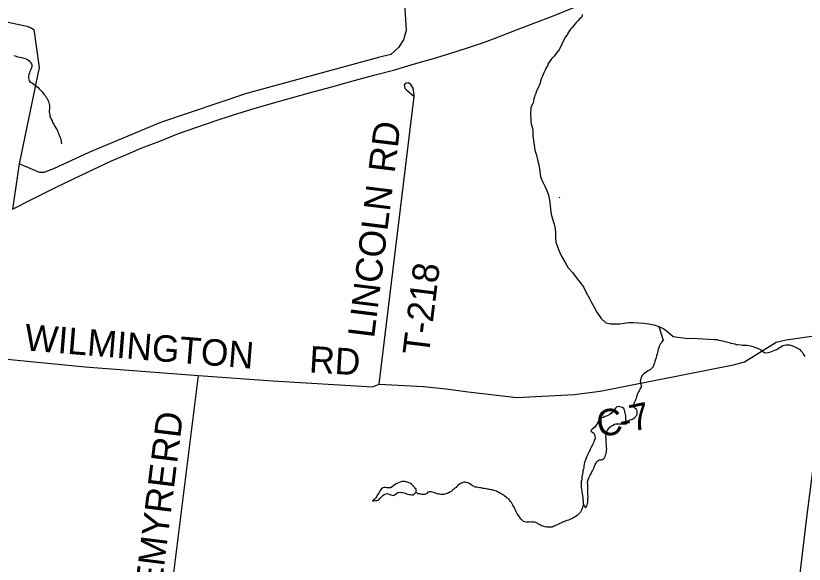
# Model space of a CAD drawing. Extents: x 0.4 to 34.4, y -2.1 to 19.9.
# Drawn here: x 5.402 to 7.097, y 14.193 to 15.372 of the extents above; entities that cross this region are included whole.
import ezdxf

# ---------------------------------------------------------------- set-up
doc = ezdxf.new("R2010")
doc.units = 0
for name, color, linetype in [('GM_X_County_Road', 7, 'Continuous'), ('GM_X_County_Road_Text', 7, 'Continuous'), ('GM_X_Interstate_Route', 7, 'Continuous'), ('GM_X_Minor_Lake', 7, 'Continuous'), ('GM_X_Minor_River', 7, 'Continuous'), ('GM_X_Township_Road', 7, 'Continuous'), ('GM_X_Township_Road_Text', 7, 'Continuous')]:
    doc.layers.add(name, color=color, linetype=linetype)

msp = doc.modelspace()

# ---------------------------------------------------------------- linework, layer by layer
at = {"layer": 'GM_X_County_Road'}
for points in [[(6.4553, 16.1829), (6.4553, 16.1828), (6.4575, 16.1516), (6.4573, 16.1428), (6.5066, 15.488), (6.5033, 15.474), (6.4918, 15.4678), (6.2441, 15.51), (6.2361, 15.5067), (6.232, 15.492), (6.2416, 15.34), (6.2359, 15.3204), (6.2246, 15.3035), (6.208, 15.2886), (6.1821, 15.2819), (5.8983, 15.2045), (5.7135, 15.1423), (5.5589, 15.0776), (5.4835, 15.0426), (5.4621, 15.035), (5.453, 15.0352), (5.438, 15.0411), (5.4094, 15.0538)], [(5.1472, 16.0652), (5.1472, 16.0652), (5.1927, 15.4283), (5.1962, 15.413), (5.2017, 15.4034), (5.2182, 15.394), (5.4257, 15.3499), (5.4355, 15.3459), (5.4407, 15.3424), (5.4524, 15.2606), (5.4094, 15.0538), (5.3948, 14.9559)], [(5.3532, 14.6364), (5.551, 14.6173), (5.7946, 14.5981), (5.9549, 14.5868), (6.1689, 14.5743), (6.183, 14.58), (6.2787, 14.5749), (6.327, 14.5697), (6.3748, 14.5632), (6.4792, 14.5513), (6.6022, 14.5578), (6.6586, 14.5646), (6.9447, 14.6216), (6.9686, 14.6277), (7.0369, 14.6701), (7.058, 14.675), (7.1535, 14.6887)]]:
    msp.add_lwpolyline(points, dxfattribs=at)
at = {"layer": 'GM_X_Interstate_Route'}
msp.add_lwpolyline([(5.3948, 14.9559), (5.4385, 14.9781), (5.4875, 15.0026), (5.5279, 15.0219), (5.5682, 15.0412), (5.6082, 15.0597), (5.642, 15.0742), (5.6732, 15.0879), (5.7116, 15.1026), (5.7519, 15.1185), (5.791, 15.1325), (5.8309, 15.1458), (5.8678, 15.1579), (5.9092, 15.1711), (5.9536, 15.184), (5.995, 15.1957), (6.0356, 15.207), (6.0812, 15.2194), (6.1245, 15.2311), (6.172, 15.2439), (6.2137, 15.2549), (6.2593, 15.2684), (6.3003, 15.2801), (6.3353, 15.2908), (6.3729, 15.3029), (6.4116, 15.3162), (6.4455, 15.3287), (6.4785, 15.342), (6.5181, 15.3564), (6.5561, 15.3712), (6.6089, 15.3922)], dxfattribs=at)
at = {"layer": 'GM_X_Minor_Lake'}
for points in [[(6.7148, 14.497), (6.7138, 14.5046), (6.7135, 14.5077), (6.7132, 14.5115), (6.7128, 14.5145), (6.7122, 14.5176), (6.7115, 14.521), (6.7104, 14.5237), (6.7089, 14.5272), (6.7063, 14.5299), (6.7029, 14.5307), (6.6999, 14.5311), (6.6972, 14.5316), (6.6941, 14.5308), (6.6914, 14.5282), (6.6894, 14.5252), (6.6871, 14.5222), (6.6832, 14.5181), (6.6789, 14.5148), (6.6762, 14.5133), (6.672, 14.5107), (6.6685, 14.51), (6.6654, 14.5085), (6.6627, 14.5074), (6.66, 14.5064), (6.6562, 14.5034), (6.6538, 14.4992), (6.6526, 14.4962), (6.651, 14.4936), (6.6486, 14.4898), (6.6467, 14.4872), (6.6428, 14.4838), (6.6389, 14.4809), (6.6381, 14.4782), (6.6415, 14.4763), (6.6448, 14.4743), (6.6463, 14.4716), (6.647, 14.4682), (6.6473, 14.4655), (6.6468, 14.4617), (6.6456, 14.4591), (6.6448, 14.4564), (6.644, 14.4538), (6.6428, 14.4511), (6.6408, 14.4481), (6.6396, 14.4455), (6.6376, 14.4417), (6.636, 14.4375), (6.6348, 14.4349), (6.632, 14.4296)], [(6.6223, 14.3215), (6.626, 14.3148), (6.6287, 14.3167), (6.6307, 14.3204), (6.6312, 14.3235), (6.6316, 14.3269), (6.6317, 14.3296), (6.6321, 14.3334), (6.6322, 14.3368), (6.6323, 14.3398), (6.632, 14.3429), (6.632, 14.3459), (6.6321, 14.3486), (6.6318, 14.352), (6.6319, 14.3547), (6.6319, 14.3585), (6.632, 14.3619), (6.6317, 14.3646), (6.6314, 14.3684), (6.6319, 14.3718), (6.6327, 14.3744), (6.6339, 14.3782), (6.6351, 14.3816), (6.6367, 14.3843), (6.6387, 14.3876), (6.6403, 14.391), (6.6419, 14.3937), (6.6431, 14.3963), (6.6451, 14.4008), (6.6463, 14.4035), (6.6475, 14.4069), (6.6491, 14.4095), (6.6507, 14.4129), (6.6542, 14.4159), (6.6569, 14.417), (6.6603, 14.4173), (6.663, 14.4176), (6.6661, 14.4199), (6.6681, 14.4225), (6.6693, 14.4251), (6.6701, 14.4278), (6.6713, 14.4308), (6.6718, 14.4342), (6.6722, 14.438), (6.6723, 14.4418), (6.672, 14.4445), (6.6721, 14.4479), (6.6718, 14.4506), (6.6715, 14.454), (6.6711, 14.4567), (6.6712, 14.4593), (6.6709, 14.4628), (6.6706, 14.4654), (6.6706, 14.4681), (6.6715, 14.4708), (6.6719, 14.4742), (6.6727, 14.4772), (6.6743, 14.4806), (6.6767, 14.4844), (6.6791, 14.4874), (6.6829, 14.49), (6.6864, 14.4918), (6.6891, 14.4936), (6.6922, 14.4947), (6.696, 14.4947), (6.7002, 14.4946), (6.7029, 14.4945), (6.7059, 14.4945), (6.7086, 14.4944), (6.7113, 14.4944), (6.7151, 14.4943)], [(6.7151, 14.4943), (6.7148, 14.497)], [(6.632, 14.4296), (6.6304, 14.4258), (6.6292, 14.4232), (6.6272, 14.4187), (6.626, 14.4153), (6.6248, 14.4119), (6.6239, 14.4081), (6.6234, 14.4039), (6.623, 14.4005), (6.6222, 14.3978), (6.6209, 14.3925), (6.62, 14.3865), (6.6199, 14.3838), (6.6191, 14.3812), (6.6186, 14.3743), (6.6177, 14.3709), (6.6173, 14.3663), (6.6175, 14.3618), (6.6174, 14.3576), (6.6181, 14.3542), (6.6188, 14.35), (6.6191, 14.3473), (6.6198, 14.3446), (6.6205, 14.34), (6.6208, 14.3362), (6.6214, 14.332), (6.6218, 14.3294), (6.6217, 14.3267), (6.622, 14.3236), (6.6223, 14.3215)], [(6.263, 14.3477), (6.2631, 14.3504), (6.2628, 14.3538), (6.2602, 14.3565), (6.2587, 14.3592), (6.2557, 14.3619), (6.2531, 14.365), (6.2493, 14.367), (6.2459, 14.3682), (6.2414, 14.3698), (6.2387, 14.3703), (6.2349, 14.3703), (6.2322, 14.3704), (6.2284, 14.3693), (6.2249, 14.3678), (6.2215, 14.366), (6.2176, 14.3638), (6.2149, 14.3619), (6.211, 14.359), (6.2075, 14.3571), (6.2037, 14.3568), (6.1999, 14.3569), (6.1969, 14.3573), (6.1942, 14.3577), (6.1908, 14.3571), (6.1877, 14.3541), (6.1857, 14.3511), (6.1841, 14.3484), (6.1825, 14.3458), (6.1793, 14.3409), (6.1774, 14.3379), (6.1754, 14.3349), (6.1723, 14.3315), (6.1692, 14.3289), (6.1726, 14.3288), (6.1757, 14.3296), (6.1791, 14.3299), (6.1822, 14.3313), (6.1849, 14.3343), (6.188, 14.3377), (6.1912, 14.3407), (6.1943, 14.3425), (6.1977, 14.344), (6.2004, 14.3447), (6.2042, 14.3435), (6.2083, 14.3419), (6.2114, 14.3411), (6.2148, 14.3406), (6.2162, 14.3418)], [(6.2162, 14.3418), (6.2202, 14.3447), (6.2237, 14.3469), (6.2279, 14.3476), (6.2313, 14.3472), (6.234, 14.3467), (6.2367, 14.3463), (6.2408, 14.3447), (6.2442, 14.3435), (6.2476, 14.3423), (6.2503, 14.3423), (6.2537, 14.3422), (6.2572, 14.3418), (6.263, 14.3477)]]:
    msp.add_lwpolyline(points, dxfattribs=at)
at = {"layer": 'GM_X_Minor_River'}
for points in [[(6.62, 15.3744), (6.6192, 15.3717), (6.6187, 15.369), (6.6148, 15.3657), (6.6113, 15.362), (6.6066, 15.3571), (6.6043, 15.3545), (6.6008, 15.35), (6.5976, 15.3462), (6.5945, 15.3429), (6.5914, 15.3387), (6.5886, 15.3346), (6.5878, 15.3316), (6.5831, 15.3259), (6.5807, 15.321), (6.5779, 15.3158), (6.5751, 15.3097), (6.5727, 15.3044), (6.5703, 15.2995), (6.5687, 15.2969), (6.5655, 15.2928), (6.5624, 15.2883), (6.5593, 15.2849), (6.5546, 15.2797), (6.5522, 15.277), (6.5487, 15.2721), (6.5459, 15.2676), (6.5455, 15.265), (6.5415, 15.259), (6.5403, 15.2552), (6.5371, 15.2491), (6.5359, 15.2457), (6.5343, 15.2423), (6.5327, 15.239), (6.5315, 15.2356), (6.5302, 15.2318), (6.529, 15.2272), (6.527, 15.2219), (6.5258, 15.2193), (6.5234, 15.2144), (6.5222, 15.2117), (6.521, 15.2083), (6.5197, 15.2049), (6.5181, 15.2004), (6.5173, 15.1974), (6.516, 15.1932), (6.5143, 15.1849), (6.5127, 15.1815), (6.5103, 15.1766), (6.5091, 15.1736), (6.509, 15.1694), (6.5085, 15.1637), (6.5088, 15.1572), (6.509, 15.1515), (6.5093, 15.1473), (6.5096, 15.1446), (6.5103, 15.1397), (6.5117, 15.1343), (6.5127, 15.1305), (6.5134, 15.1259), (6.5137, 15.1243)], [(5.3979, 15.2864), (5.4029, 15.2851), (5.4055, 15.2839), (5.4112, 15.2827), (5.4142, 15.2819), (5.4195, 15.2806), (5.4226, 15.2802), (5.426, 15.2786), (5.4294, 15.2767), (5.4324, 15.2743), (5.4338, 15.2716), (5.4361, 15.2689), (5.4368, 15.2662), (5.4367, 15.2632), (5.4362, 15.2602), (5.4354, 15.2575), (5.4326, 15.2522), (5.4314, 15.2492), (5.4298, 15.2454), (5.4294, 15.2416), (5.4293, 15.2382), (5.43, 15.2355), (5.4307, 15.2329)], [(5.4307, 15.2329), (5.4329, 15.2294), (5.4355, 15.2282), (5.4382, 15.227), (5.4412, 15.2247), (5.4445, 15.222), (5.4472, 15.2196), (5.4502, 15.2177), (5.4524, 15.2146), (5.4557, 15.2115), (5.458, 15.2088), (5.4602, 15.2061), (5.4624, 15.203), (5.465, 15.2003), (5.4676, 15.1964), (5.4695, 15.1937), (5.4713, 15.1906), (5.4724, 15.1876), (5.4734, 15.1845), (5.4741, 15.1818), (5.4745, 15.1792), (5.4744, 15.1754), (5.4743, 15.1716), (5.4742, 15.1678), (5.4741, 15.1647), (5.4745, 15.1617), (5.4752, 15.1586), (5.4755, 15.1556), (5.4769, 15.1529), (5.4784, 15.1494), (5.4802, 15.146), (5.4813, 15.1425), (5.4839, 15.139), (5.4853, 15.1356), (5.4868, 15.1329), (5.4886, 15.1294), (5.4908, 15.1264), (5.4927, 15.1229), (5.4934, 15.1202), (5.4948, 15.1172), (5.4966, 15.1114), (5.4981, 15.1087), (5.4987, 15.1053), (5.4994, 15.1026), (5.4998, 15.0999), (5.5001, 15.0969)], [(6.5137, 15.1243), (6.5137, 15.1136), (6.5151, 15.1037), (6.5164, 15.0934), (6.5182, 15.0828), (6.5211, 15.0721), (6.5239, 15.0618), (6.5268, 15.0515), (6.5285, 15.0379), (6.5302, 15.0257), (6.5342, 15.0154), (6.5394, 15.0054), (6.5438, 14.9959), (6.5474, 14.986), (6.5492, 14.9757), (6.5509, 14.9647), (6.5519, 14.9552), (6.5533, 14.9453), (6.5561, 14.935), (6.5594, 14.9236), (6.5619, 14.9137), (6.5621, 14.9042), (6.562, 14.8947), (6.563, 14.8852), (6.5666, 14.8753), (6.571, 14.8642), (6.5762, 14.8539), (6.5824, 14.8428), (6.5898, 14.8302), (6.5988, 14.8198), (6.6066, 14.8094), (6.6144, 14.7991), (6.6222, 14.7891), (6.6285, 14.7772), (6.6348, 14.7657), (6.6399, 14.7554), (6.6462, 14.7443), (6.6514, 14.7344), (6.6607, 14.7213), (6.6704, 14.7117), (6.6802, 14.7096), (6.6901, 14.7095), (6.7003, 14.7097), (6.7102, 14.7107), (6.7197, 14.7121), (6.7292, 14.7127), (6.741, 14.7117), (6.7512, 14.7112), (6.7626, 14.7099), (6.7739, 14.7074), (6.7841, 14.7038), (6.7951, 14.6991), (6.8048, 14.6914), (6.8153, 14.6821), (6.8255, 14.6808), (6.8369, 14.6791), (6.8471, 14.6778), (6.8555, 14.6784)], [(6.57, 14.9807), (6.5717, 14.9818)], [(6.7841, 14.7038), (6.7934, 14.6744), (6.7911, 14.671), (6.7891, 14.668), (6.7872, 14.6658), (6.7855, 14.6616), (6.7843, 14.6586), (6.7835, 14.6563), (6.7831, 14.654), (6.7823, 14.6518), (6.7814, 14.648), (6.7806, 14.6449), (6.7797, 14.6408), (6.7785, 14.6381), (6.7777, 14.634), (6.7768, 14.6313), (6.776, 14.629), (6.7752, 14.6249), (6.774, 14.6219), (6.7728, 14.6196), (6.772, 14.6173), (6.77, 14.6151), (6.7677, 14.6128), (6.7657, 14.6106), (6.763, 14.6091), (6.7603, 14.608), (6.7572, 14.6054), (6.7545, 14.6036), (6.7518, 14.6013), (6.7494, 14.5991), (6.7475, 14.5965), (6.7463, 14.5938), (6.7455, 14.5916), (6.745, 14.5893), (6.7446, 14.5862), (6.7449, 14.584), (6.7456, 14.5817), (6.7459, 14.5794), (6.7466, 14.5767), (6.7462, 14.5733), (6.7446, 14.5706), (6.7434, 14.568), (6.7418, 14.5657), (6.7406, 14.5635), (6.7394, 14.5608), (6.7382, 14.5578), (6.737, 14.5552), (6.7362, 14.5525), (6.7354, 14.5491), (6.7341, 14.5461), (6.7333, 14.5438), (6.7321, 14.5408), (6.7309, 14.5382), (6.7301, 14.5351), (6.7297, 14.5329), (6.73, 14.5306), (6.733, 14.5286), (6.7356, 14.5267), (6.7367, 14.5244), (6.737, 14.5221), (6.7374, 14.5194), (6.7373, 14.5171), (6.7373, 14.5148), (6.7361, 14.5126), (6.7345, 14.5103), (6.7325, 14.5077), (6.7298, 14.5055), (6.7271, 14.504), (6.7248, 14.5029), (6.7221, 14.5022), (6.7198, 14.5011), (6.7148, 14.497)], [(6.8555, 14.6784), (6.9044, 14.6762), (6.909, 14.6757), (6.9135, 14.6745), (6.9177, 14.6736), (6.9211, 14.6732), (6.9242, 14.6724), (6.9299, 14.6707), (6.9359, 14.6691), (6.9389, 14.6679), (6.9435, 14.6671), (6.9477, 14.6662), (6.9507, 14.6654), (6.9534, 14.665), (6.9614, 14.6641), (6.964, 14.664), (6.9694, 14.6636), (6.9735, 14.6635), (6.9777, 14.663), (6.9815, 14.6622), (6.9842, 14.6618), (6.9883, 14.6602)], [(6.9883, 14.6602), (6.9917, 14.659), (6.9944, 14.6578), (6.997, 14.6566), (6.9997, 14.6558), (7.0031, 14.6542), (7.0065, 14.6518), (7.0109, 14.6479), (7.014, 14.6471), (7.0193, 14.6482), (7.0228, 14.6489), (7.0266, 14.6503), (7.0305, 14.6514), (7.0336, 14.6529), (7.0378, 14.6547), (7.0416, 14.6569), (7.0443, 14.6584), (7.0478, 14.6606), (7.0513, 14.6628), (7.054, 14.6639), (7.0582, 14.6646), (7.0609, 14.6645), (7.0651, 14.6641), (7.0677, 14.6636), (7.0704, 14.6628), (7.0768, 14.6604), (7.0809, 14.6581), (7.0877, 14.6541), (7.0896, 14.6514), (7.0933, 14.648), (7.0948, 14.6449), (7.0966, 14.6418), (7.0984, 14.6391)], [(6.3584, 14.3662), (6.356, 14.3651), (6.3529, 14.3624), (6.3506, 14.3606), (6.3486, 14.358), (6.3456, 14.3565), (6.3436, 14.3542), (6.3409, 14.3524), (6.3393, 14.3501), (6.3358, 14.3483), (6.3335, 14.3468), (6.33, 14.345), (6.327, 14.3439), (6.3243, 14.3432), (6.322, 14.3428), (6.3182, 14.3425), (6.3155, 14.3426), (6.3132, 14.3434), (6.3109, 14.3434), (6.3079, 14.3442), (6.3056, 14.3451), (6.303, 14.3459), (6.3, 14.3471), (6.2973, 14.3479), (6.295, 14.3483), (6.2928, 14.3483), (6.2905, 14.348), (6.2882, 14.3473), (6.2854, 14.345), (6.2831, 14.3436), (6.2804, 14.3428), (6.2781, 14.3429), (6.2759, 14.3429), (6.2736, 14.343), (6.2713, 14.3434), (6.269, 14.3438), (6.2667, 14.3439), (6.263, 14.3477)], [(6.6223, 14.3215), (6.6187, 14.31), (6.6178, 14.3077), (6.6159, 14.3043), (6.6135, 14.3021), (6.6108, 14.2995), (6.6092, 14.2972), (6.6058, 14.2954), (6.603, 14.2936), (6.5996, 14.2917), (6.5973, 14.2906), (6.5942, 14.2895), (6.5899, 14.2877), (6.5869, 14.2866), (6.583, 14.2852), (6.5807, 14.2841), (6.5776, 14.283), (6.5753, 14.2819), (6.5715, 14.2801), (6.5684, 14.2786), (6.5661, 14.2775), (6.5622, 14.2757), (6.5599, 14.2746), (6.5572, 14.2735), (6.5549, 14.2724), (6.5518, 14.272), (6.5496, 14.2721), (6.5473, 14.2721), (6.5435, 14.2726), (6.5404, 14.273), (6.5378, 14.2738), (6.5355, 14.2746), (6.5329, 14.2751), (6.5298, 14.2766), (6.5276, 14.2778), (6.5253, 14.279), (6.5231, 14.2806), (6.5201, 14.2825), (6.5174, 14.2833), (6.5147, 14.2834), (6.5124, 14.2834), (6.5102, 14.2835), (6.5063, 14.2832), (6.5041, 14.2832), (6.5018, 14.2832), (6.4991, 14.2833), (6.4961, 14.2837), (6.4934, 14.2845), (6.4908, 14.2872), (6.4886, 14.2896), (6.486, 14.2923), (6.4845, 14.2953), (6.4815, 14.2996), (6.4789, 14.3023), (6.4775, 14.305), (6.476, 14.3092), (6.4746, 14.3115), (6.4731, 14.3157), (6.4709, 14.3196), (6.4691, 14.3223), (6.468, 14.3253), (6.4654, 14.3277), (6.4632, 14.3307), (6.4617, 14.3331), (6.4587, 14.335), (6.4565, 14.337), (6.4535, 14.3393), (6.4512, 14.3409), (6.4489, 14.342), (6.4467, 14.3432), (6.4441, 14.3448), (6.4403, 14.3471), (6.4376, 14.3483), (6.4354, 14.3495), (6.4327, 14.3503), (6.4297, 14.3515), (6.4263, 14.3523), (6.4236, 14.3528), (6.4206, 14.3536), (6.4183, 14.354), (6.4161, 14.3544), (6.4126, 14.3549), (6.41, 14.3553), (6.4069, 14.3557), (6.4047, 14.3562), (6.402, 14.3566), (6.399, 14.357), (6.3959, 14.3579), (6.3933, 14.3583), (6.3906, 14.3587), (6.3872, 14.3599), (6.3838, 14.3615), (6.3804, 14.3638), (6.3767, 14.3662), (6.3736, 14.3678), (6.3706, 14.3686), (6.3683, 14.369), (6.3661, 14.3691), (6.363, 14.3684), (6.3607, 14.3673), (6.3584, 14.3662)]]:
    msp.add_lwpolyline(points, dxfattribs=at)
at = {"layer": 'GM_X_Township_Road'}
for points in [[(6.183, 14.58), (6.2587, 15.1984), (6.2586, 15.2018), (6.2561, 15.2166), (6.2513, 15.2243), (6.2456, 15.2278), (6.2415, 15.2267), (6.2372, 15.2233), (6.2383, 15.2161), (6.2417, 15.213), (6.2586, 15.1984)], [(6.0486, 13.0593), (6.2023, 13.1806), (6.9275, 13.7533), (6.9437, 13.7644), (6.9532, 13.768), (7.0189, 13.7683), (7.0311, 13.7726), (7.0415, 13.7819), (7.1029, 14.2928), (7.1535, 14.6887)], [(6.2023, 13.1806), (5.8073, 13.8455), (5.7894, 13.8608), (5.7182, 13.8651), (5.7038, 13.8704), (5.7946, 14.5981)]]:
    msp.add_lwpolyline(points, dxfattribs=at)

# ---------------------------------------------------------------- texts
at = {"layer": 'GM_X_County_Road_Text'}
for s, height, rotation, p in [('WILMINGTON', 0.05682, 355.3719, (5.4194, 14.6527)), ('RD', 0.05682, 356.5467, (6.0316, 14.6053)), ('C', 0.0568, 8.2598, (6.6549, 14.4661)), ('7', 0.0568, 11.5527, (6.7274, 14.478)), ('-', 0.0568, 11.4408, (6.7045, 14.4734))]:
    msp.add_text(s, height=height, rotation=rotation, dxfattribs=at).set_placement(p)
at = {"layer": 'GM_X_Township_Road_Text'}
for s, rotation, p in [('RD', 83.0589, (6.2164, 15.0323)), ('LINCOLN', 82.9336, (6.1722, 14.6774)), ('T-218', 82.9789, (6.2898, 14.6401)), ('RD', 83.0589, (5.7489, 14.4082)), ('SETTLEMYRE', 82.9015, (5.6855, 13.9016))]:
    msp.add_text(s, height=0.05682, rotation=rotation, dxfattribs=at).set_placement(p)

doc.saveas('drawing.dxf')
